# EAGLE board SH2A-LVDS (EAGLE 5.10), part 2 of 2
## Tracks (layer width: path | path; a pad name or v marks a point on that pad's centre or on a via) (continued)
DE0_21  (via drill 0.3) (continued)
  Top 0.127: DE0.24 31.62,58.29 31.62,66.17 SP3.24 25.53,72.26 v25.53,72.77 25.53,73.66 25.57,73.7 LCD.10
  Bottom 0.127: v25.53,72.77 25.53,74.54 LCD.10
DE0_22  (via drill 0.3)
  Top 0.127: DE0.25 SP3.25 33.02,65.79 31.62,67.18 31.62,67.82 26.54,72.9 v26.54,73.41 26.54,73.66 26.57,73.69 LCD.8
  Bottom 0.127: v26.54,73.41 26.54,74.55 LCD.8
DE0_23  (via drill 0.3)
  Top 0.127: DE0.26 34.16,58.29 34.16,66.17 SP3.26 v27.56,72.77 27.56,73.66 27.57,73.67 LCD.6
  Bottom 0.127: v27.56,72.77 LCD.6
DE0_24
  Top 0.127: DE0.27 SP3.27
DE0_25
  Top 0.127: DE0.28 36.7,58.29 36.7,66.17 SP3.28
DE0_26
  Top 0.127: DE0.31 SP3.31
DE0_27
  Top 0.127: DE0.32 41.78,58.29 41.78,66.17 SP3.32
DE0_28
  Top 0.127: DE0.33 SP3.33
DE0_29
  Top 0.127: DE0.34 44.32,58.29 44.32,66.17 SP3.34
DE0_30
  Top 0.127: DE0.35 SP3.35
DE0_31
  Top 0.127: DE0.36 46.86,58.29 46.86,66.17 SP3.36
DE0_32
  Top 0.127: DE0.37 SP3.37
DE0_33
  Top 0.127: DE0.38 49.4,58.29 49.4,66.17 SP3.38
DE0_34
  Top 0.127: DE0.39 SP3.39
DE0_35
  Top 0.127: DE0.40 51.94,58.29 51.94,66.17 SP3.40
DE0_GND  (via drill 0.3)
  Top 0.127: REV.2 11.07,75.54 v10.92,75.69 10.54,75.31 10.57,75.16 REV.1 | 12.07,75.43 REV.4 | 12.07,75.43 12.06,75.18 | 12.07,75.43 v12.32,75.68 v12.32,75.69 12.57,75.44 REV.5 | REV.10 15.07,75.65 v15.11,75.69 | REV.14 17.07,75.39 17.02,75.44 v17.02,75.69 | REV.18 19.07,75.67 v19.05,75.69 | v21.08,75.69 21.08,74.59 REV.22 | v23.11,75.69 23.11,75.31 23.07,75.27 REV.26 | v25.02,75.69 25.02,74.63 REV.30 | REV.32 26.07,75.66 v26.04,75.69
  Bottom 0.127: REV.1 10.57,75.34 v10.92,75.69 | v12.32,75.69 12.06,75.44 REV.4 12.07,75.44 v12.32,75.69 | v12.32,75.69 v12.32,75.7 | 12.57,75.44 REV.5 | 12.57,75.44 12.36,75.65 | 15.07,75.65 REV.10 | 15.07,75.65 v15.11,75.69 v17.02,75.69 | 17.07,74.6 17.07,75.26 17.02,75.44 v17.02,75.69 | REV.22 v21.07,75.68 v21.08,75.69 | REV.26 23.07,75.27 23.11,75.31 v23.11,75.69 | v25.02,75.69 25.02,75.31 25.07,75.26 REV.30 25.07,75.62 25.15,75.69 v26.04,75.69 | v26.04,75.69 26.04,75.56 | REV.32 26.04,74.61 26.04,75.56 | DE0.30 39.37,58.42 39.37,63.5 SP3.29 SP3.30 38.1,77.22 36.7,78.61 27.81,78.61 26.04,76.83 | DE0.12 13.97,58.42 13.97,63.5 SP3.9 SP3.10 12.57,67.44 12.57,75.44 | 12.36,75.65 15.07,75.65 | 12.36,75.65 v12.32,75.69 | v19.05,75.69 v21.08,75.69 | v21.08,75.69 v23.11,75.69 | v23.11,75.69 v25.02,75.69 | 26.04,76.83 v26.04,75.69 | v25.02,75.69 26.04,76.83 | v12.32,75.69 v10.92,75.69 | REV.18 19.07,75.67 v19.05,75.69 | v17.02,75.69 v19.05,75.69 | v17.02,75.69 17.02,75.18 | 17.07,74.6 REV.14 | 17.02,75.18 17.07,74.6 | 17.02,75.18 17.02,74.68 | v26.04,75.69 26.16,75.56 26.04,75.56 | REV.2 11.07,75.54 v10.92,75.69
  pour Bottom (isolate 0.254): 0.64,79.38 0.64,53.98 52.7,53.98 52.7,79.38
DE1_3V3  (via drill 0.3)
  Top 0.127: 66.93,14.1 66.93,15.37 IC102.5 | v63.5,32.89 63.5,33.4 64.39,33.4 | 64.39,33.4 64.52,33.4 | 64.39,33.4 IC101.48 | v67.44,41.66 67.82,41.27 67.82,40.39 IC101.32 | 67.56,48.39 67.94,48.39 R101.1 67.94,48.64 | IC101.22 72.77,37.97 74.3,37.97 v75.69,39.37 | 69.85,27.18 R109.2 | v71.12,27.43 71.12,27.18
  Top 0.61: X1.4 87.63,34.92 X1.5 | 71.12,27.18 69.85,27.18 | v68.96,49.66 67.94,48.64
  Top 1.016: 66.93,14.1 66.55,13.72 v66.17,13.72
  Bottom 0.127: C110.1 71.75,5.33 70.87,6.22 68.71,6.22 QG101.4 64.77,10.16 62.1,10.16 62.1,15.24 | 64.77,12.95 66.17,12.95 | 66.17,12.95 67.31,12.95 C114.1 | 64.77,12.95 62.48,15.24 62.1,15.24 | 64.77,12.95 C115.1 | 62.1,15.24 DE1.29 59.69,16.51 54.99,16.51 54.99,49.28 64.64,49.28 64.77,49.15 | v67.44,41.66 66.8,41.66 66.04,40.89 C103.1 68.58,40.26 | 64.77,49.15 67.31,49.15 | 67.31,49.15 68.71,49.15 | 68.71,49.15 70.48,49.15 | 67.31,49.15 R103.2 | 70.48,49.15 70.61,49.28 74.55,49.28 LED101.A 75.56,51.82 94.87,51.82 94.87,47.72 X1.9 94.49,47.37 94.11,46.99 94.11,45.47 93.47,44.83 90.93,44.83 | 70.48,49.15 R104.2 | 87,40.26 84.45,40.26 R117.1 84.45,40.13 83.31,40.13 83.31,37.08 | 89.53,40.26 87,40.26 | 87,40.26 R116.1 | 90.93,40.26 89.53,40.26 | 90.93,40.26 92.08,40.26 R114.1 | 89.53,40.26 R115.1 | 90.93,44.83 90.93,40.26 | 77.72,37.08 77.72,34.92 | 77.72,37.08 77.72,37.34 R107.2 77.6,38.19 77.6,39.37 v75.69,39.37 | 77.72,34.92 R108.2 | 77.72,34.92 77.72,34.04 74.8,34.04 74.8,33.02 | 74.8,33.02 74.8,32.51 71.12,28.83 v71.12,27.43 67.31,27.43 67.31,32.13 | X1.5 87,36.2 87,35.18 86.87,35.05 84.45,35.05 83.31,36.2 83.31,37.08 | 83.31,37.08 81.28,37.08 | 90.93,44.83 90.93,45.97 82.04,45.97 X1.12 79.58,43.56 73.41,43.56 71.5,41.66 71.5,40.64 71.12,40.26 68.58,40.26 | 64.77,49.15 R102.2 | C101.1 64.77,32.13 64.9,32.13 | 67.31,32.13 C102.1 | 81.28,37.08 C109.1 | 68.58,40.26 C104.1 | v63.5,32.89 64.39,32 64.9,32.13 | 67.31,32.13 64.9,32.13 | 74.8,33.02 C108.1 | 81.28,37.08 77.72,37.08 | 66.17,12.95 v66.17,13.72 | v68.96,49.66 68.96,49.4 68.71,49.15
  pour Bottom (isolate 0.254): 53.98,52.7 99.06,52.7 99.06,29.21 73.66,29.21 73.66,24.13 74.93,24.13 74.93,27.94 99.06,27.94 99.06,0.64 53.98,0.64
DE1_5V  (via drill 0.3)
  Top 0.127: C111.1 64.64,21.08
  Top 1.016: v63.25,23.24 64.64,21.84 C111.1
  Bottom 0.127: 65.53,23.24 64.9,23.24 IC103.3 | v63.25,23.24 63.12,23.37
  Bottom 1.016: v63.25,23.24 63.12,23.24 63.12,23.37 61.59,24.89 61.59,36.2 DE1.11
  Bottom 1.778: v63.25,23.24 64.9,23.24
DE1_ACT  (via drill 0.3)
  Top 0.127: v71.63,45.97 71.63,45.59 70.87,44.83 70.87,40.39 IC101.26
  Bottom 0.127: 71.63,46.74 76.2,46.74 79.5,50.29 80.26,51.05 88.9,51.05 90.42,49.53 R113.1 | v71.63,45.97 71.63,46.74 | 71.63,46.74 70.87,46.74 70.48,47.12 R104.1 70.48,47.37
DE1_BCLK
  Top 0.127: DE1.39 60.71,2.54 65.41,7.24 66.17,7.24 66.93,8 66.93,8.76 IC102.16
DE1_CKS0
  Top 0.127: 64.39,15.37 64.39,15.24 | 64.39,15.37 64.39,16.13 64.14,16.38 63.37,16.38 62.99,16 62.99,14.48 60.2,11.68 58.17,11.68 DE1.32 | 64.39,15.37 IC102.9
DE1_CKS1
  Top 0.127: DE1.33 59.69,10.79 63.75,14.86 63.75,15.24 IC102.10
DE1_CKS2
  Top 0.127: DE1.34 58.55,8.76 60.07,8.76 60.83,8 63.63,8 63.82,8.19 IC102.11
DE1_CKS3
  Top 0.127: DE1.35 59.69,7.75 64.01,7.75 64.39,8.13 64.39,8.76 IC102.12
DE1_CLK
  Top 0.127: IC101.34 66.8,40.39 66.8,41.91 65.15,43.56 65.15,47.62 60.71,52.07 58.42,52.07 DE1.2 DE1.4
DE1_COL
  Top 0.127: DE1.15 60.58,33.91 60.58,34.67 62.36,36.45 64.39,36.45 IC101.42
DE1_CRS
  Top 0.127: DE1.13 60.71,35.56 62.61,37.47 64.39,37.47 IC101.40
DE1_DEM0
  Top 0.127: IC102.6 66.29,15.37 66.29,16.13 65.15,17.27 60.2,17.27 DE1.27
DE1_DEM1
  Top 0.127: IC102.7 65.66,15.37 65.66,16.13 64.77,17.02 60.45,17.02 60.07,16.64 58.29,16.64 DE1.28
DE1_GND  (via drill 0.3)
  Top 0.127: 72.77,34.42 IC101.15 71.22,34.45 v71.25,34.29 | 65.79,41.27 65.79,39.24 65.83,39.29 IC101.36 65.83,41.19 65.91,41.27 65.83,41.23 65.79,41.27 | 66.29,41.27 IC101.35 | 66.29,41.27 66.29,39.37 67.06,38.61 v67.31,38.61 69.34,38.61 69.98,39.24 71.63,39.24 72.77,40.39 72.77,41.91 74.42,41.91 | 65.79,41.27 66.29,41.27 | 83.95,33.53 X1.8 83.19,33.66 | RLIN.2 RLIN.3 94.87,24.13 94.74,24 94.74,9.91 92.71,7.87 92.71,4.06 92.65,4 LOUT.S 92.08,2.67 79.38,2.67 | 77.6,35.56 v77.6,41.91 74.42,41.91 | 68.58,24.51 71.12,24.51 | 71.12,24.51 C113.2 | 62.23,18.8 62.23,23.75 62.99,24.51 68.58,24.51 | 71.12,24.51 72.26,24.51 72.26,19.94 71.63,19.3 70.1,19.3 68.33,17.53 68.33,15.37 IC102.3 68.33,15.3 68.33,13.97 | 68.58,24.51 C112.2 | 77.6,35.56 76.07,35.56 75.18,36.45 72.77,36.45 IC101.19 71.58,36.45 v71.25,36.83 | 72.77,34.42 71.25,34.42 v71.25,34.29 | 72.77,34.42 73.79,34.42 74.17,34.04 75.82,34.04 77.72,32.13 77.72,29.97 83.19,29.97 83.19,33.66 | 77.6,35.56 83.19,35.56 83.19,33.66 | 69.85,3.56 67.31,3.56 C117.2 | 69.85,3.56 74.42,3.56 74.42,3.3 75.06,2.67 79.38,2.67 | 69.85,3.56 C116.2 | 79.38,2.67 ROUT.S 79.38,4.06 | 63.25,18.8 64.64,18.8 C111.2 | 62.23,18.8 63.25,18.8 | 56.13,18.8 62.23,18.8 | 56.13,15.24 56.13,18.8 | 56.13,11.3 58.42,11.3 58.42,9.53 58.93,9.02 61.09,9.02 v63.37,11.3 66.04,11.3 66.8,12.06 66.8,12.45 68.33,13.97 | 56.13,6.35 62.23,6.35 | 75.18,2.67 75.18,0.89 56.13,0.89 56.13,6.35 | 56.13,6.35 56.13,11.3 | 56.13,11.3 56.13,15.24 | 56.13,15.24 DE1.30 | 56.13,26.92 60.07,26.92 61.85,28.7 61.85,33.91 64.39,33.91 IC101.47 65.31,33.95 65.67,34.3 v66.04,34.3 | 56.13,18.8 56.13,26.92
  Top 0.127: 56.13,26.92 56.13,38.1 | 65.79,41.27 65.79,41.78 63.63,43.94 63.63,48.39 60.2,51.82 58.8,51.82 58.29,51.31 58.29,44.45 56.13,44.45 | 56.13,38.1 56.13,44.45 | 74.42,41.91 74.42,52.45 56.13,52.45 56.13,44.45 | 56.13,38.1 DE1.12 | v71.25,34.29 66.8,34.29 66.16,34.3 v66.04,34.3 | v66.04,34.3 v66.04,34.29 | v66.04,34.3 | 63.25,18.8 v63.25,18.54 | v68.71,11.43 68.71,13.59 68.33,13.97
  Bottom 0.127: 68.58,38.23 C104.2 68.58,38.61 | 77.6,40.64 R111.2 | 64.77,11.18 C115.2 64.77,11.3 | 64.9,18.29 64.9,18.41 64.9,18.54 IC103.1 | 67.31,11.18 C114.2 | 76.33,6.35 R120.1 76.45,6.35 | C110.2 71.75,3.68 64.52,3.68 63.5,2.67 QG101.2 v66.04,2.54 | R121.1 89.03,6.35 | ROUT.S 79.38,4.06 | v67.31,38.61 66.29,38.61 66.04,38.35 65.87,38.65 66.29,38.73 66.04,38.61 C103.2 | 64.77,34.16 C101.2 64.98,33.87 64.77,33.91 65.15,34.29 v66.04,34.29 | 67.31,34.16 C102.2 | 66.04,36.83 C106.2 | 71.25,38.1 C107.2 | 81.28,34.67 C109.2 | 71.29,35.56 71.25,35.56 | 71.25,33.02 C108.2 | v71.25,34.29 71.29,35.56 | 71.29,35.56 C105.2
  Bottom 1.016: 68.58,38.61 66.04,38.61 66.04,36.83 67.31,36.83 67.31,34.16 64.77,34.16 | v77.6,41.91 77.6,40.64 | 64.77,11.18 67.31,11.18 68.45,11.18 v68.71,11.43 | 81.28,34.67 82.8,34.67 X1.8 | 71.25,33.02 71.25,35.56 v71.25,36.83 71.25,38.1 | v63.25,18.54 63.37,18.41 | v63.37,11.3 64.77,11.3 | R121.1 90.81,6.35 92.08,5.08 LOUT.S | 76.33,6.35 78.11,6.35 79.38,5.08 79.38,4.06
  Bottom 1.778: 63.37,18.41 64.9,18.41
  pour Top (isolate 0.254): 53.98,0.64 99.06,0.64 99.06,27.94 67.31,27.94 67.31,29.21 99.06,29.21 99.06,52.7 53.98,52.7
DE1_LIN
  Top 0.127: 68.96,16.13 68.96,15.37 IC102.2 | 81.79,24.64 C119.1
  Top 0.305: 68.96,16.13 68.96,16.76 70.48,18.29 75.44,18.29 81.79,24.64
DE1_LNK  (via drill 0.3)
  Top 0.127: v69.47,45.21 69.85,44.83 69.85,40.39 IC101.28
  Bottom 0.127: 65.15,47.88 64.77,47.5 R102.1 | R112.1 81.03,49.53 75.95,44.45 70.23,44.45 v69.47,45.21 68.83,45.21 68.33,45.72 66.29,45.72 65.15,46.86 65.15,47.88 | R102.1 65.15,47.88 | R102.1 64.77,47.37 61.34,47.37 DE1.5 DE1.6
DE1_LOUT  (via drill 0.3)
  Top 0.127: 68.96,9.53 68.96,8.76 IC102.19
  Top 0.305: 68.96,9.53 68.96,10.03 69.85,10.92 69.85,11.43 73.79,15.37 77.22,15.37 78.23,16.38 85.34,16.38 v87,14.73
  Bottom 0.127: 88.27,13.46 C121.1
  Bottom 0.305: v87,14.73 87.63,14.73 88.27,14.1 88.27,13.46
DE1_LRCK
  Top 0.127: DE1.37 62.48,5.08 65.15,7.75 65.41,7.75 65.66,8 65.66,8.76 IC102.14
DE1_MCLK
  Top 0.127: DE1.38 58.17,4.06 61.85,4.06 65.28,7.49 65.79,7.49 66.29,8 66.29,8.76 IC102.15
  Bottom 0.127: DE1.38 58.17,6.1 63.25,6.1 63.37,6.22 QG101.3
DE1_MDC  (via drill 0.3)
  Top 0.127: v68.2,42.16 68.33,42.04 68.33,40.39 IC101.31
  Bottom 0.127: v68.2,42.16 67.44,42.93 61.09,42.93 60.07,41.91 58.42,41.91 DE1.10
DE1_MDIO  (via drill 0.3)
  Top 0.127: R101.2 67.94,46.61 67.18,45.85 67.18,44.07 v67.82,43.43 68.07,43.43 68.83,42.67 68.83,40.39 IC101.30
  Bottom 0.127: DE1.7 67.31,43.18 67.56,43.43 v67.82,43.43
DE1_MII
  Bottom 0.127: DE1.9 61.09,40.64 62.23,41.66 R106.1
DE1_PDIN
  Top 0.127: DE1.40 58.17,1.52 60.07,1.52 65.53,6.99 66.55,6.99 67.56,8 67.56,8.76 IC102.17
DE1_RIN
  Top 0.127: 69.6,15.75 69.6,16 69.53,15.94 IC102.1 | 81.79,21.34 81.92,21.08 C118.1
  Top 0.305: 69.6,15.75 69.98,15.75 71.37,17.14 76.71,17.14 80.9,21.34 81.79,21.34
DE1_ROUT  (via drill 0.3)
  Top 0.127: IC102.20 69.6,8.64
  Top 0.305: 69.6,8.64 v74.17,13.21
  Bottom 0.127: 75.56,13.46 C120.1
  Bottom 0.305: v74.17,13.21 75.56,13.21 75.56,13.46
DE1_RST_N  (via drill 0.3)
  Top 0.127: v67.94,44.32 69.34,42.93 69.34,40.39 IC101.29
  Bottom 0.127: v67.94,44.32 67.56,44.32 66.67,43.43 61.09,43.43 60.33,44.2 58.17,44.2 DE1.8
DE1_RXCLK
  Top 0.127: DE1.1 59.69,50.55 62.87,47.37 62.87,38.86 63.25,38.48 64.39,38.48 IC101.38
DE1_RXD0
  Top 0.127: DE1.18 58.42,31.75 59.94,31.75 60.83,32.64 60.83,34.54 62.23,35.94 64.52,35.94 IC101.43
DE1_RXD1
  Top 0.127: DE1.17 61.09,31.88 61.09,34.42 62.1,35.43 64.39,35.43 IC101.44
DE1_RXD2
  Top 0.127: DE1.20 58.17,28.96 59.56,28.96 61.34,30.73 61.34,34.29 61.98,34.92 64.39,34.92 IC101.45
DE1_RXD3
  Top 0.127: DE1.19 61.59,29.84 61.59,34.16 61.85,34.42 64.39,34.42 IC101.46
DE1_RXDV  (via drill 0.3)
  Top 0.127: IC101.39 64.39,37.97 62.87,37.97 v62.61,38.23 62.61,37.97 61.34,36.7 58.29,36.7 DE1.14
  Bottom 0.127: v62.61,38.23 62.61,38.35 62.23,38.73 R106.2
DE1_RXER
  Top 0.127: DE1.16 58.67,34.54 60.07,34.54 62.48,36.96 64.39,36.96 IC101.41
DE1_SNI
  Top 0.127: DE1.25 61.09,21.72 61.09,23.5 64.52,26.92 67.31,26.92 R110.1
DE1_SPD  (via drill 0.3)
  Top 0.127: IC101.27 70.36,40.39 70.36,45.47 v70.74,45.85 70.74,46.74 R105.1
  Bottom 0.127: v70.74,45.85 70.36,46.23 70.1,46.23 68.96,47.37 67.31,47.37 R103.1
DE1_STDI
  Top 0.127: DE1.36 58.17,6.6 60.2,6.6 61.09,7.49 64.39,7.49 65.02,8.13 65.02,8.76 IC102.13
DE1_STDO
  Top 0.127: DE1.31 60.83,12.7 62.74,14.61 62.74,16.13 63.37,16.76 64.26,16.76 65.02,16 65.02,15.37 IC102.8
DE1_TXCLK  (via drill 0.3)
  Top 0.127: v64.9,30.86 65.41,30.86 65.79,31.24 65.79,32 IC101.1
  Bottom 0.127: v64.9,30.86 64.01,30.86 62.48,32.38 62.48,36.45 60.96,37.97 60.96,38.48 60.07,39.37 56.77,39.37 55.88,40.26 55.88,46.1 56.9,47.12 58.55,47.12 DE1.3
DE1_TXD0
  Top 0.127: DE1.21 61.47,25.4 66.8,30.73 66.8,32 IC101.3
DE1_TXD1
  Top 0.127: DE1.24 58.55,24.26 60.71,24.26 67.31,30.86 67.31,32.13 IC101.4
DE1_TXD2
  Top 0.127: DE1.23 67.82,30.99 67.82,32 IC101.5
DE1_TXD3
  Top 0.127: IC101.6 68.33,32 68.33,29.84 67.31,28.83 R110.2 67.31,28.57 65.79,28.57 60.83,23.62 60.83,22.35 60.2,21.72 59.44,21.72 58.04,20.32 DE1.26
DE1_TXEN
  Top 0.127: DE1.22 58.29,26.54 62.23,26.54 66.29,30.61 66.29,32 IC101.2
DE1_VA  (via drill 0.3)
  Top 0.127: 67.63,16.57 67.69,16.51 | 67.63,16.57 67.44,16.76 | IC102.4 67.63,16.57 | 67.63,16.57 67.69,16.38 | 69.98,20.83 69.85,20.32 68.58,20.32 68.26,20.64
  Top 0.406: 67.69,16.13 67.69,16.38 67.69,16.51
  Top 1.016: 68.58,20.95 C112.1 | 67.44,16.76 67.44,19.81 68.26,20.64 68.58,20.95 | 68.58,20.95 v68.96,20.95 | 68.96,20.83 69.98,20.83 C113.1
  Bottom 1.676: v68.96,20.95 IC103.2
  Bottom 6.452: v68.96,20.95 IC103.4 75.69,20.95
DE1_VCOM
  Top 0.127: 69.85,5.33 C116.1 | C117.1 67.31,5.33 | 68.33,8.76 IC102.18
  Top 0.305: 68.33,7.49 68.33,8.76
  Top 1.016: 68.33,5.33 69.85,5.33 | 68.33,5.33 68.33,7.49 | 67.31,5.33 68.33,5.33
DONE  (via drill 0.3)
  Top 0.127: v8.64,14.73 9.14,14.73 10.92,16.51 17.02,16.51 18.41,17.91 18.41,19.43 IC3.54 | v8.64,7.62 8.89,7.62 9.91,6.6 R14.2 9.53,6.35
  Bottom 0.127: v8.64,7.62 v8.64,14.73
HPD1  (via drill 0.3)
  Top 0.127: DIGITAL.19 43.88,36.39 43.69,36.2 43.69,35.43 43.81,35.31 v43.81,33.27
  Bottom 0.127: v43.81,33.27 43.81,33.66 44.45,34.29 44.45,35.17 IC10.9 44.45,35.23 44.45,36.45 44.83,36.83 47.12,36.83 48.39,35.56 R27.2
ICSPC
  Bottom 0.127: PIC.5 58.8,69.85 58.17,70.48 CONF.P$15
ICSPD
  Bottom 0.127: PIC.4 62.74,67.44 57.78,67.44 56.77,68.45 56.39,68.45 56.26,68.58 CONF.P$14
INIT_B  (via drill 0.3)
  Top 0.127: v11.18,20.57 12.7,20.57 14.48,22.35 14.99,22.35 IC3.48
  Bottom 0.127: IC8.2 13.34,8.51 12.7,9.14 | 10.16,6.73 IC6.8 10.16,7.87 11.18,8.89 12.45,8.89 12.7,9.14 | v11.18,20.57 11.18,15.37 12.06,14.48 12.06,12.45 12.32,12.19 12.45,12.19 12.7,11.94 12.7,9.14
LED_ACT
  Bottom 0.127: R113.2 92.96,49.53 92.96,49.4 92.71,49.15 92.71,46.61 92.08,45.97 X1.10
LED_LNK
  Bottom 0.127: R112.2 83.31,49.53 84.45,48.39 84.45,47.5 84.58,47.5 X1.11
LED_SPD
  Top 0.127: LED101.K 73.03,48.39 70.48,48.39 R105.2
MCLR
  Bottom 0.127: PIC.1 61.72,59.69 61.59,59.56 57.66,59.56 57.15,60.07 57.15,60.83 56.39,61.59 55.63,61.59 55.12,62.1 55.12,65.47 CONF.P$12
MOSI  (via drill 0.3)
  Top 0.127: v11.68,22.1 12.95,23.37 14.48,23.37 14.54,23.3 IC3.46
  Bottom 0.127: IC7.5 17.91,11.05 17.91,11.56 17.14,12.32 IC5.1 17.14,14.22 15.88,15.49 12.32,15.49 11.94,15.88 11.94,19.68 12.32,20.07 12.32,21.46 v11.68,22.1
N$1
  Top 0.127: C118.2 81.92,19.05
  Top 0.305: 81.92,19.05 RLIN.1
N$2
  Bottom 0.127: R19.2 38.23,14.86 | 40.26,19.27 HOST.1
  Bottom 1.016: 38.23,14.86 39.62,14.86 40.26,15.49 40.26,19.27
N$3  (via drill 0.3)
  Top 0.127: v70.74,72.26 71.12,72.64 LED201.A
  Bottom 0.127: v70.74,72.26 70.74,71.12 R209.1
N$4
  Bottom 0.127: R20.2 38.1,21.21 38.23,21.34 39.83,21.34 HOST.2
N$5
  Bottom 0.127: R21.2 38.1,23.37 38.23,23.5 39.98,23.5 HOST.3
N$6
  Bottom 0.127: DEV.2 43.34,23.66 42.93,23.24 42.58,23.24 R22.2
N$7  (via drill 0.3)
  Top 0.127: 66.04,38.23 65.28,38.99 64.52,38.99 IC101.37 | 72.64,35.94 IC101.18 | 71.12,38.48 72.64,38.48 | 72.64,38.48 IC101.23 | 72.64,38.48 73.79,38.48 | 71.75,35.94 72.64,35.94 | 72.64,35.94 73.66,35.94
  Top 0.305: 73.79,38.48 74.3,38.99 v74.3,39.12 | 71.12,35.69 71.37,35.94 71.75,35.94 | 73.66,35.94 74.3,35.94 74.55,35.69
  Top 1.016: 66.04,38.23 66.04,35.56 v66.17,35.43 69.6,35.43 69.98,35.69 | 69.98,35.69 69.98,37.34 71.12,38.48 | 69.98,35.69 71.12,35.69 | 74.55,35.69 v74.68,35.69
  Bottom 0.127: C105.1 73.28,35.56 73.41,35.69 | 64.01,36.83 C106.1 | 73.28,38.1 C107.1 73.15,38.1
  Bottom 1.016: 73.28,35.56 73.28,38.1 v74.3,39.12 | 64.01,36.83 64.01,36.2 64.77,35.43 v66.17,35.43 | v74.68,35.69 73.41,35.69
N$9
  Bottom 0.127: DEV.3 43.69,22.86 42.93,22.1 42.58,21.97 R23.2
N$10
  Bottom 0.127: R6.1 32.6,12.91 LED1.A
N$14  (via drill 0.3)
  Top 0.127: v79.76,31.37 76.2,34.92 74.17,34.92 73.66,35.43 72.77,35.43 IC101.17
  Bottom 0.127: 92.46,36.2 92.08,36.2 R114.2 | v79.76,31.37 80.26,31.88 91.06,31.88 92.46,33.27 92.46,36.2 | 92.46,36.2 X1.1
N$15  (via drill 0.3)
  Top 0.127: v78.36,31.37 78.87,31.88 76.07,34.67 74.04,34.67 73.79,34.92 72.77,34.92 IC101.16
  Bottom 0.127: R115.2 89.53,38.48 91.44,36.58 X1.2 89.92,32.13 79.12,32.13 v78.36,31.37
N$16  (via drill 0.3)
  Top 0.127: v76.83,32 75.18,33.66 73.91,33.66 73.62,33.95 IC101.14
  Bottom 0.127: R116.2 87,38.48 87.76,37.72 88.65,37.72 X1.3 90.17,33.53 89.03,32.38 77.22,32.38 v76.83,32
N$17
  Top 0.127: 81.92,26.67 C119.2 81.92,26.16
  Top 0.305: 81.92,26.67 RLIN.4
N$18
  Bottom 1.016: R118.2 76.58,9.02 77.34,9.78 77.34,12.32 78.87,13.84 79.32,13.84 ROUT.T
N$19
  Bottom 1.016: R119.2 89.11,8.98 90.04,9.78 90.04,12.45 91.31,13.84 92.02,13.84 LOUT.T
N$21
  Bottom 0.127: R121.2 87.5,6.35
  Bottom 1.016: R121.2 87.25,6.22 87.25,8.34 R119.1 87.25,8.89 87.25,9.78 88.27,10.92 C121.2
N$22  (via drill 0.3)
  Top 0.127: v75.44,32 75.95,32.51 75.06,33.4 72.77,33.4 IC101.13
  Bottom 0.127: R117.2 84.45,38.48 85.47,37.47 87.76,37.47 88.77,36.45 88.77,35.56 86.87,33.66 X1.6 85.34,32.64 76.07,32.64 v75.44,32
N$23
  Bottom 1.016: R120.2 74.55,6.35 74.55,9.11 R118.1 74.55,9.53 74.55,10.03 75.44,11.18 75.4,11.68 C120.2
N$29
  Top 0.127: R109.1 69.85,28.83 68.83,29.84 68.83,32 IC101.7
N$43  (via drill 0.3)
  Top 0.127: v74.93,40.64 73.28,38.99 72.77,38.99 IC101.24
  Bottom 0.127: v74.93,40.64 R111.1
N$44  (via drill 0.3)
  Top 0.127: v75.06,37.47 72.64,37.47 IC101.21
  Bottom 0.127: v75.06,37.47 75.69,37.47 75.95,37.72 75.95,38.1 R107.1 76.07,38.1
N$45  (via drill 0.3)
  Top 0.127: v76.33,36.32 75.95,36.83 74.17,36.83 74.04,36.96 73.03,36.96 IC101.20
  Bottom 0.127: v76.33,36.32 76.33,35.31 75.95,35.05 76.07,34.92 R108.1
POW3  (via drill 0.3)
  Top 0.127: 31.92,7.96 C3.1 | 29.21,7.24 C2.1
  Top 1.016: v33.15,6.48 32.13,7.49 | 32.13,7.49 31.92,7.71 31.92,7.96 | 29.21,7.24 31.88,7.24 32.13,7.49
  Bottom 0.127: 33.15,8.74 IC1.4 32.79,8.64 31.75,8.64 31.37,8.76 | v33.15,6.48 33.02,6.35 | R1.1 28.19,4.7
  Bottom 1.778: 28.19,4.7 31.37,4.7 31.37,6.35
  Bottom 2.54: 33.02,6.35 IC1.2
  Bottom 5.08: 33.15,8.74 v33.15,6.48 | 31.37,6.35 31.37,8.76
PROG_B
  Top 0.127: IC3.100 30.73,33.4 31.62,33.4 32.51,34.29 32.51,36.83 R7.1 32.64,36.83 32.64,39.5 IC9.2
SCL1  (via drill 0.3)
  Top 0.127: DIGITAL.15 44.23,38.39 43.69,38.35 43.43,38.35 42.93,37.85 v42.55,37.85
  Bottom 0.127: IC10.3 42.55,40.98 42.55,39.75 41.91,39.12 41.91,38.23 42.29,37.85 v42.55,37.85 42.93,37.85 43.43,38.35 47.37,38.35 47.88,38.86 47.88,40.01 48.13,40.26 48.3,40.26 R26.1
SDA1  (via drill 0.3)
  Top 0.127: DIGITAL.16 43.86,37.89 43.81,37.85 43.43,37.85 42.67,37.08 42.67,36.45 v42.8,36.32
  Bottom 0.127: 42.55,35.34 42.55,34.67 | 42.55,35.34 42.55,36.07 v42.8,36.32 42.67,36.45 42.67,37.08 43.69,38.1 R25.1 | IC10.12 42.55,35.34
TCK  (via drill 0.3)
  Top 0.127: v27.94,36.7 27.3,36.7 23.5,40.51 23.11,40.51 21.59,42.04 JTAG.1
  Bottom 0.127: 18.92,42.29 19.05,42.42 R2.1 19.18,42.29 18.92,42.29 | JTAG.1 19.94,46.99 17.91,44.96 17.91,43.31 18.92,42.29 | IC4.2 26.67,37.72 26.67,37.08 27.05,36.7 v27.94,36.7
TDI
  Bottom 0.127: 32.89,42.29 32,43.18 32,46.99 JTAG.9 | 32.89,42.29 32.89,40.51 31.37,38.99 25.02,38.99 24.77,38.73 24.77,37.85 IC4.5 | 32.89,42.29 32.89,42.42 R5.1 33.02,42.04
TDO  (via drill 0.3)
  Top 0.127: v25.53,44.58 25.53,45.59 JTAG.3
  Bottom 0.127: v25.53,44.58 25.4,44.45 IC4.11
TMS
  Bottom 0.127: R4.1 30.48,42.29 29.59,43.18 29.59,44.07 JTAG.5 24.13,44.45 24.13,43.56 IC4.9
VCCINT  (via drill 0.3)
  Top 0.127: 12.7,48.6 C4.1 | IC3.17 20.86,34 v21.59,33.27 | IC3.38 16.51,27.3 | IC3.66 24.36,21.23 v24.13,21.46 | IC3.81 29.9,23.8 28.96,24.77
  Top 1.016: 16.51,27.3 17.27,27.3 17.27,28.19 v17.65,28.57 | 24.13,22.73 v24.13,21.46 | 22.73,28.57 22.73,32.13 v21.59,33.27 | v28.96,26.04 28.96,24.77 25.91,24.89
  Top 1.27: v11.43,47.24 11.43,48.64 12.7,48.6 | C4.1 C5.1
  Top 2.54: v17.65,28.57 22.73,28.57 24.13,27.18 24.13,24.89 | 24.13,24.89 24.13,22.73 | 24.13,24.89 25.91,24.89
  Bottom 0.127: 20.36,33.27 C11.1 | 17.27,27.77 C14.1 17.27,27.3 | 22.95,21.46 C12.1 | 28.96,24.77 28.57,24.55 C13.1
  Bottom 0.61: v24.13,21.46 22.95,21.46
  Bottom 1.016: 20.36,33.27 v21.59,33.27 21.59,34.29 | v17.65,28.57 17.27,28.19 17.27,27.77 | v28.96,26.04 28.96,24.77
  Bottom 1.27: IC2.4 11.43,42.42 12.7,41.15 16.76,41.15 21.59,36.32 21.59,34.29
  Bottom 1.778: 11.43,47.37 IC2.2
  Bottom 3.81: IC2.4 v11.43,47.24 11.43,47.37
XCE  (via drill 0.3)
  Top 0.127: IC3.29 14.55,31.8 14.48,31.75 14.1,31.75 v13.46,32.38
  Bottom 0.127: R8.1 12.7,33.27 v13.46,32.38 14.35,31.5 14.35,29.72 13.46,28.83 13.46,28.07 11.81,26.42 11.81,23.5 10.79,22.48 10.79,21.72 11.3,21.21 11.43,21.21 11.81,20.83 11.81,20.32 11.43,19.94 11.43,15.62 12.06,14.99 13.08,14.99 13.97,14.1 IC6.4 13.97,9.78 14.61,9.14 IC8.1
XCK  (via drill 0.3)
  Top 0.127: v13.46,31.37 14.35,31.37 14.41,31.3 IC3.30
  Bottom 0.127: 12.7,31.37 12.7,31.24 R9.1 12.57,31.11 12.7,31.37 | IC8.6 12.06,11.94 11.43,12.57 IC6.2 11.43,14.73 10.92,15.24 10.92,19.94 10.54,20.32 10.54,22.61 11.56,23.62 11.56,26.54 13.21,28.19 13.21,28.96 14.1,29.84 14.1,30.73 v13.46,31.37 12.7,31.37
XDI  (via drill 0.3)
  Top 0.127: v13.46,30.23 13.84,30.23 14.41,30.8 IC3.31
  Bottom 0.127: 12.57,28.96 13.46,29.84 v13.46,30.23 | IC8.5 10.79,11.81 10.16,12.45 IC6.1 10.16,16.26 8.38,18.03 8.38,20.83 11.3,23.75 11.3,26.67 12.57,27.94 12.57,28.96 | 12.57,28.96 12.32,28.83 R10.1
XTCK  (via drill 0.3)
  Top 0.127: v30.61,20.57 30.61,21.21 30.73,21.21 IC3.76 | v30.61,34.67 30.35,34.67 29.72,35.31 v29.72,36.45
  Bottom 0.127: v30.61,20.57 v30.61,34.67 | v29.72,36.45 29.34,36.07 26.92,36.07 25.91,37.08 26.04,37.85 IC4.3
XTDI  (via drill 0.3)
  Top 0.127: v25.53,39.62 25.53,38.86 27.05,37.34 28.19,37.34 28.57,36.96 28.57,35.94 28.32,35.69 28.32,35.18 IC3.2
  Bottom 0.127: v25.53,39.62 25.27,39.62 24.13,38.48 24.13,37.85 IC4.6
XTDO  (via drill 0.3)
  Top 0.127: v29.21,20.95 29.21,19.81 28.96,19.56 IC3.75 | v29.72,34.42 29.46,34.67 29.46,35.56 29.08,35.94 29.08,37.21 28.45,37.85 27.3,37.85 27.05,38.1 v27.05,39.62
  Bottom 0.127: v29.21,20.95 30.35,22.1 30.35,33.78 v29.72,34.42 | v27.05,39.62 27.05,40.26 26.29,41.02 26.29,42.16 26.04,42.42 | 26.04,42.42 24.77,42.42 24.13,41.78 24.13,40.89 23.75,40.51 23.11,40.51 22.1,41.53 22.1,42.16 21.59,42.16 R3.1 | 26.04,43.43 26.04,43.69 | 26.04,42.42 26.04,43.43 | 26.04,43.43 IC4.12
XTMS  (via drill 0.3)
  Top 0.127: v23.37,41.15 24.26,40.26 25.91,40.26 26.29,39.88 26.29,38.48 27.18,37.59 28.32,37.59 28.83,37.08 28.83,35.18 IC3.1
  Bottom 0.127: v23.37,41.15 22.86,41.66 22.86,42.55 23.37,43.05 23.37,43.43 IC4.8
